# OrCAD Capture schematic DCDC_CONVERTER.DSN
size A
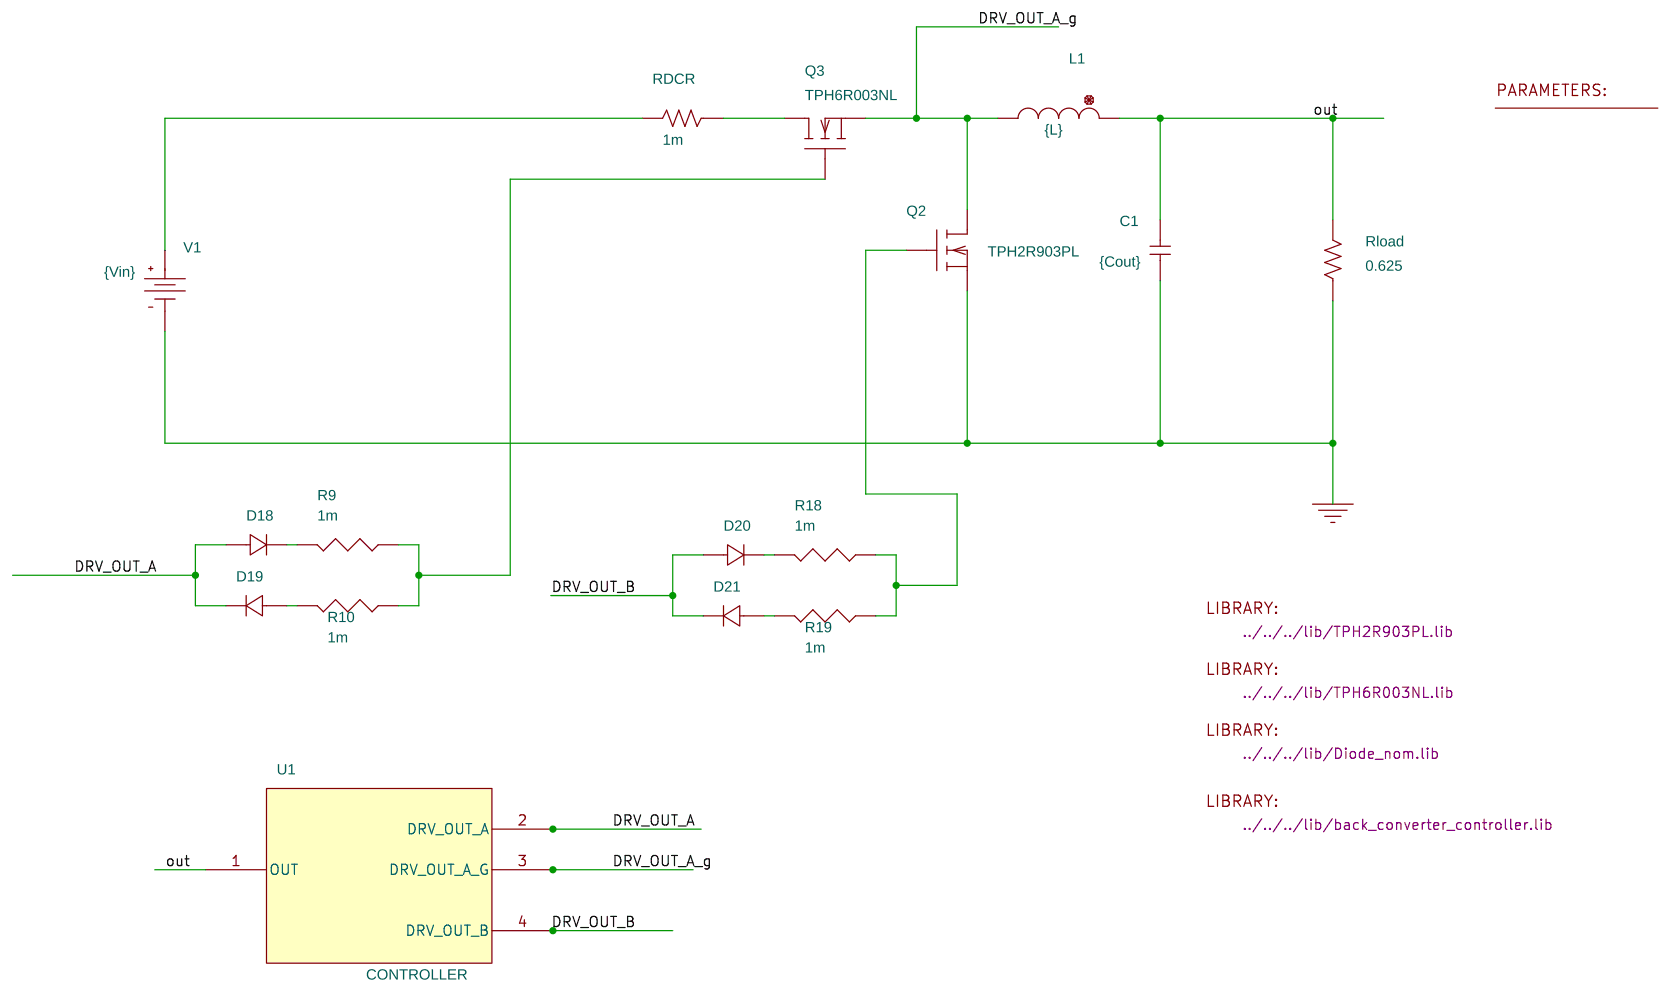
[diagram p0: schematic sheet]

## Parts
1  PARAM
C1  {Cout}  [RAD/CK05]
D18  Diode_nom
D19  Diode_nom
D20  Diode_nom
D21  Diode_nom
L1  {L}  [DISC/.350x.175/LS.200x.100/.034]
LIB2  LIB
LIB4  LIB
LIB5  LIB
LIB6  LIB
Q2  TPH2R903PL
Q3  TPH6R003NL
R9  1m  [AXRC05]
R10  1m  [AXRC05]
R18  1m  [AXRC05]
R19  1m  [AXRC05]
RDCR  1m  [AXRC05]
Rload  0.625  [AXRC05]
U1  CONTROLLER
V1  VDC

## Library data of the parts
1 = PARAM: Cin: 0.22u; Cout: 150u; Fc: 300k; L: 3.3u; Rdrv_off_p: 0.5; Rdrv_off_s: 0.5; Rdrv_on_p: 5; Rdrv_on_s: 5; Vdrv_H: 5; Vin: 12; Vout: 5
C1 = C
D18-D21 = Diode_nom
L1 = L
LIB2 = LIB: FILENAME: ../../../lib/TPH6R003NL.lib
LIB4 = LIB: FILENAME: ../../../lib/Diode_nom.lib
LIB5 = LIB: FILENAME: ../../../lib/TPH2R903PL.lib
LIB6 = LIB: FILENAME: ../../../lib/back_converter_controller.lib
Q2 = TPH2R903PL
Q3 = TPH6R003NL
R9 R10 R18 R19 = R
RDCR Rload = R_v2
U1 = CONTROLLER
V1 = VDC: DC: {Vin}

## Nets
0: C1.1 Q2.0(s) Rload.1 V1.1(-)
DRV_OUT_A: D18.0(1) D19.1(2) U1.2(DRV_OUT_A)
DRV_OUT_A_g: L1.2 Q2.2(d) Q3.0(s) U1.3(DRV_OUT_A_G)
DRV_OUT_B: D20.0(1) D21.1(2) U1.4(DRV_OUT_B)
out: C1.2 L1.1 Rload.2 U1.1(OUT)
N2325771: RDCR.2 V1.0(+)
N2325781: Q3.2(d) RDCR.1
N2325843: Q3.1(g) R9.1 R10.1
N2325885: Q2.1(g) R18.1 R19.1
N2326073: D18.1(2) R9.2
N2326099: D20.1(2) R18.2
N2326245: D19.0(1) R10.2
N2326263: D21.0(1) R19.2
